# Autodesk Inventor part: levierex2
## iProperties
Created: 2006-05
Part Number: levierex2
Document SubType Name: Modeling
Designer: Administrateur
Manufacturer: Standard
Standards Organization: Custom
Author: Administrateur
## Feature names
1. Extrusion1
2. Extrusion2
3. Miroir1 [Mirror]
4. Congé1 [Fillet]
5. Congé2 [Fillet]
6. Congé3 [Fillet]
7. Congé4 [Fillet]
8. Congé5 [Fillet]
9. Congé6 [Fillet]
10. Congé7 [Fillet]
11. Congé9 [Fillet]
